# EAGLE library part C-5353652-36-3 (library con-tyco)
ETX Express COM Express Auto generated by make-symbol-device-package-bsdl.ulp Rev. 27 Source: http://catalog.tycoelectronics.com .. ENG_CS_889092_0.5mm_FH_Conn_0906.pdf http://nordic.kontron.com/searchresult/?searchterm=etxe_designguide_v1.4.pdf
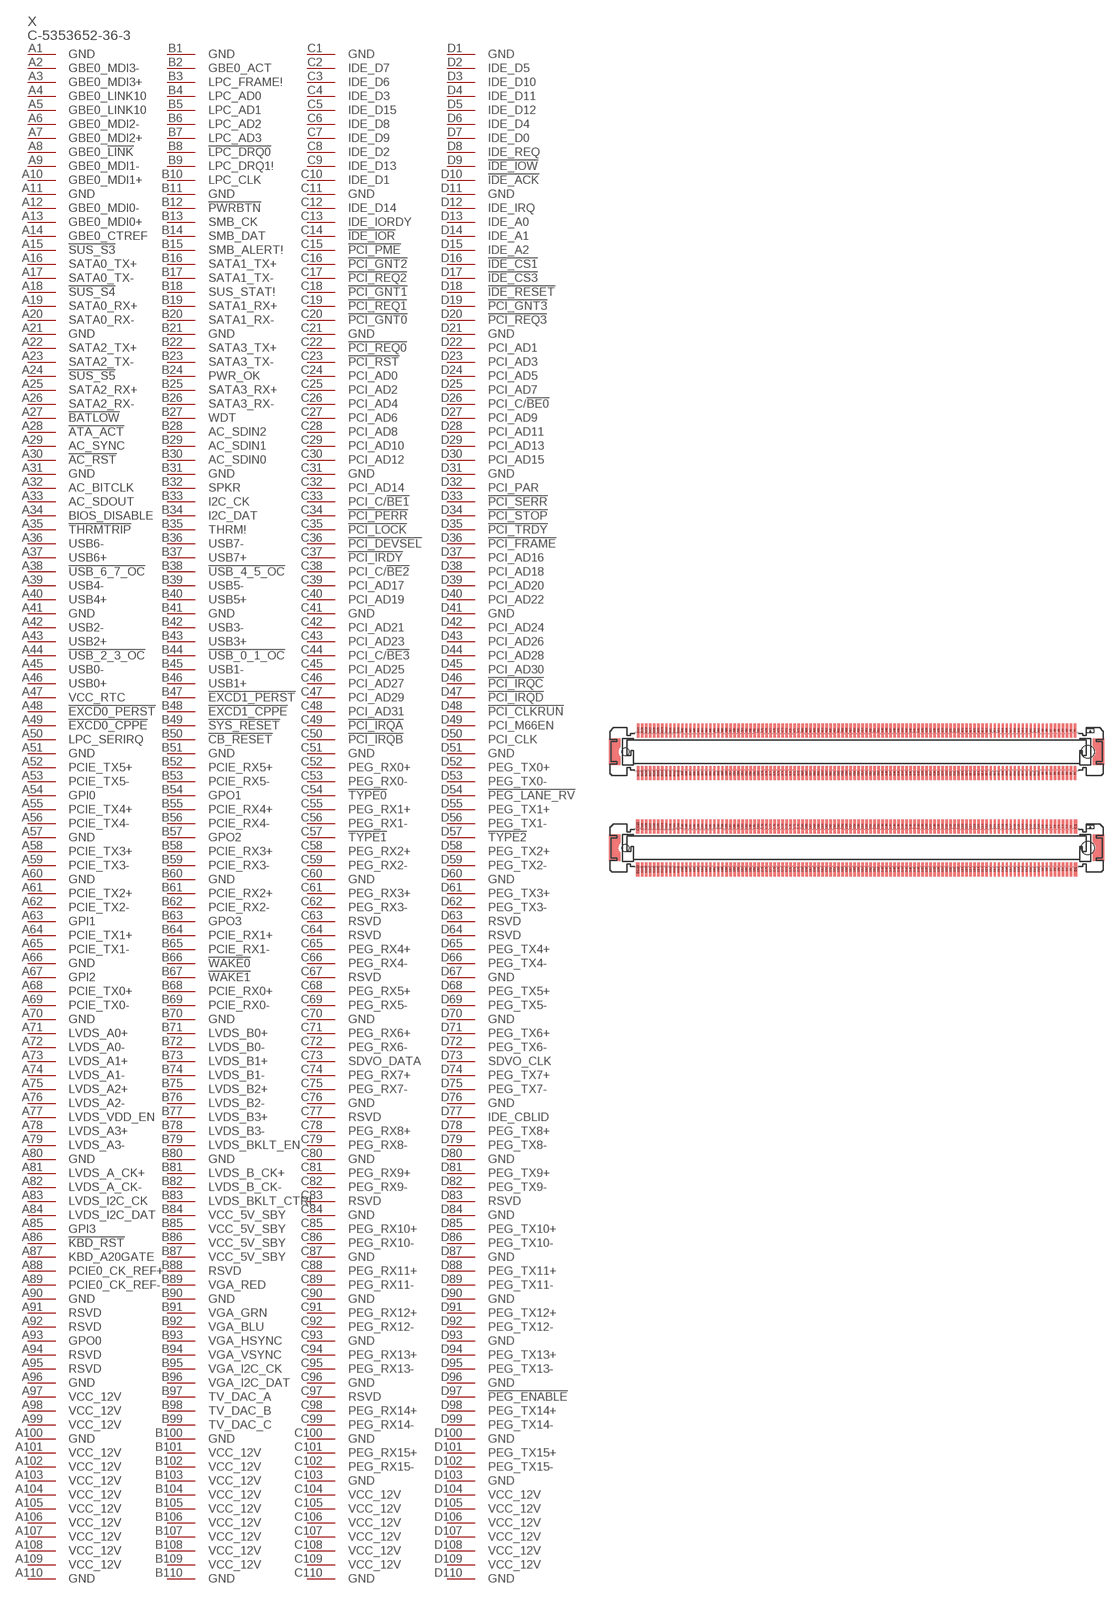
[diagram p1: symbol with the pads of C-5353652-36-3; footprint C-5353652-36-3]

Designator prefix X

## C-5353652-36-3 (OC_FARNELL: unknown; OC_NEWARK: unknown)  [C-5353652-36-3]
A1  GND  pas
A2  GBE0_MDI3-  pas
A3  GBE0_MDI3+  pas
A4  GBE0_LINK10  pas
A5  GBE0_LINK10  pas
A6  GBE0_MDI2-  pas
A7  GBE0_MDI2+  pas
A8  GBE0_!LINK  pas
A9  GBE0_MDI1-  pas
A10  GBE0_MDI1+  pas
A11  GND  pas
A12  GBE0_MDI0-  pas
A13  GBE0_MDI0+  pas
A14  GBE0_CTREF  pas
A15  !SUS_S3  pas
A16  SATA0_TX+  pas
A17  SATA0_TX-  pas
A18  !SUS_S4  pas
A19  SATA0_RX+  pas
A20  SATA0_RX-  pas
A21  GND  pas
A22  SATA2_TX+  pas
A23  SATA2_TX-  pas
A24  !SUS_S5  pas
A25  SATA2_RX+  pas
A26  SATA2_RX-  pas
A27  !BATLOW  pas
A28  !ATA_ACT  pas
A29  AC_SYNC  pas
A30  !AC_RST  pas
A31  GND  pas
A32  AC_BITCLK  pas
A33  AC_SDOUT  pas
A34  BIOS_DISABLE  pas
A35  !THRMTRIP  pas
A36  USB6-  pas
A37  USB6+  pas
A38  !USB_6_7_OC  pas
A39  USB4-  pas
A40  USB4+  pas
A41  GND  pas
A42  USB2-  pas
A43  USB2+  pas
A44  !USB_2_3_OC  pas
A45  USB0-  pas
A46  USB0+  pas
A47  VCC_RTC  pas
A48  !EXCD0_PERST  pas
A49  !EXCD0_CPPE  pas
A50  LPC_SERIRQ  pas
A51  GND  pas
A52  PCIE_TX5+  pas
A53  PCIE_TX5-  pas
A54  GPI0  pas
A55  PCIE_TX4+  pas
A56  PCIE_TX4-  pas
A57  GND  pas
A58  PCIE_TX3+  pas
A59  PCIE_TX3-  pas
A60  GND  pas
A61  PCIE_TX2+  pas
A62  PCIE_TX2-  pas
A63  GPI1  pas
A64  PCIE_TX1+  pas
A65  PCIE_TX1-  pas
A66  GND  pas
A67  GPI2  pas
A68  PCIE_TX0+  pas
A69  PCIE_TX0-  pas
A70  GND  pas
A71  LVDS_A0+  pas
A72  LVDS_A0-  pas
A73  LVDS_A1+  pas
A74  LVDS_A1-  pas
A75  LVDS_A2+  pas
A76  LVDS_A2-  pas
A77  LVDS_VDD_EN  pas
A78  LVDS_A3+  pas
A79  LVDS_A3-  pas
A80  GND  pas
A81  LVDS_A_CK+  pas
A82  LVDS_A_CK-  pas
A83  LVDS_I2C_CK  pas
A84  LVDS_I2C_DAT  pas
A85  GPI3  pas
A86  !KBD_RST  pas
A87  KBD_A20GATE  pas
A88  PCIE0_CK_REF+  pas
A89  PCIE0_CK_REF-  pas
A90  GND  pas
A91  RSVD  pas
A92  RSVD  pas
A93  GPO0  pas
A94  RSVD  pas
A95  RSVD  pas
A96  GND  pas
A97  VCC_12V  pas
A98  VCC_12V  pas
A99  VCC_12V  pas
A100  GND  pas
A101  VCC_12V  pas
A102  VCC_12V  pas
A103  VCC_12V  pas
A104  VCC_12V  pas
A105  VCC_12V  pas
A106  VCC_12V  pas
A107  VCC_12V  pas
A108  VCC_12V  pas
A109  VCC_12V  pas
A110  GND  pas
B1  GND  pas
B2  GBE0_ACT  pas
B3  LPC_FRAME!  pas
B4  LPC_AD0  pas
B5  LPC_AD1  pas
B6  LPC_AD2  pas
B7  LPC_AD3  pas
B8  !LPC_DRQ0  pas
B9  LPC_DRQ1!  pas
B10  LPC_CLK  pas
B11  GND  pas
B12  !PWRBTN  pas
B13  SMB_CK  pas
B14  SMB_DAT  pas
B15  SMB_ALERT!  pas
B16  SATA1_TX+  pas
B17  SATA1_TX-  pas
B18  SUS_STAT!  pas
B19  SATA1_RX+  pas
B20  SATA1_RX-  pas
B21  GND  pas
B22  SATA3_TX+  pas
B23  SATA3_TX-  pas
B24  PWR_OK  pas
B25  SATA3_RX+  pas
B26  SATA3_RX-  pas
B27  WDT  pas
B28  AC_SDIN2  pas
B29  AC_SDIN1  pas
B30  AC_SDIN0  pas
B31  GND  pas
B32  SPKR  pas
B33  I2C_CK  pas
B34  I2C_DAT  pas
B35  THRM!  pas
B36  USB7-  pas
B37  USB7+  pas
B38  !USB_4_5_OC  pas
B39  USB5-  pas
B40  USB5+  pas
B41  GND  pas
B42  USB3-  pas
B43  USB3+  pas
B44  !USB_0_1_OC  pas
B45  USB1-  pas
B46  USB1+  pas
B47  !EXCD1_PERST  pas
B48  !EXCD1_CPPE  pas
B49  !SYS_RESET  pas
B50  !CB_RESET  pas
B51  GND  pas
B52  PCIE_RX5+  pas
B53  PCIE_RX5-  pas
B54  GPO1  pas
B55  PCIE_RX4+  pas
B56  PCIE_RX4-  pas
B57  GPO2  pas
B58  PCIE_RX3+  pas
B59  PCIE_RX3-  pas
B60  GND  pas
B61  PCIE_RX2+  pas
B62  PCIE_RX2-  pas
B63  GPO3  pas
B64  PCIE_RX1+  pas
B65  PCIE_RX1-  pas
B66  !WAKE0  pas
B67  !WAKE1  pas
B68  PCIE_RX0+  pas
B69  PCIE_RX0-  pas
B70  GND  pas
B71  LVDS_B0+  pas
B72  LVDS_B0-  pas
B73  LVDS_B1+  pas
B74  LVDS_B1-  pas
B75  LVDS_B2+  pas
B76  LVDS_B2-  pas
B77  LVDS_B3+  pas
B78  LVDS_B3-  pas
B79  LVDS_BKLT_EN  pas
B80  GND  pas
B81  LVDS_B_CK+  pas
B82  LVDS_B_CK-  pas
B83  LVDS_BKLT_CTRL  pas
B84  VCC_5V_SBY  pas
B85  VCC_5V_SBY  pas
B86  VCC_5V_SBY  pas
B87  VCC_5V_SBY  pas
B88  RSVD  pas
B89  VGA_RED  pas
B90  GND  pas
B91  VGA_GRN  pas
B92  VGA_BLU  pas
B93  VGA_HSYNC  pas
B94  VGA_VSYNC  pas
B95  VGA_I2C_CK  pas
B96  VGA_I2C_DAT  pas
B97  TV_DAC_A  pas
B98  TV_DAC_B  pas
B99  TV_DAC_C  pas
B100  GND  pas
B101  VCC_12V  pas
B102  VCC_12V  pas
B103  VCC_12V  pas
B104  VCC_12V  pas
B105  VCC_12V  pas
B106  VCC_12V  pas
B107  VCC_12V  pas
B108  VCC_12V  pas
B109  VCC_12V  pas
B110  GND  pas
C1  GND  pas
C2  IDE_D7  pas
C3  IDE_D6  pas
C4  IDE_D3  pas
C5  IDE_D15  pas
C6  IDE_D8  pas
C7  IDE_D9  pas
C8  IDE_D2  pas
C9  IDE_D13  pas
C10  IDE_D1  pas
C11  GND  pas
C12  IDE_D14  pas
C13  IDE_IORDY  pas
C14  !IDE_IOR  pas
C15  !PCI_PME  pas
C16  !PCI_GNT2  pas
C17  !PCI_REQ2  pas
C18  !PCI_GNT1  pas
C19  !PCI_REQ1  pas
C20  !PCI_GNT0  pas
C21  GND  pas
C22  !PCI_REQ0  pas
C23  !PCI_RST  pas
C24  PCI_AD0  pas
C25  PCI_AD2  pas
C26  PCI_AD4  pas
C27  PCI_AD6  pas
C28  PCI_AD8  pas
C29  PCI_AD10  pas
C30  PCI_AD12  pas
C31  GND  pas
C32  PCI_AD14  pas
C33  PCI_C/!BE1  pas
C34  !PCI_PERR  pas
C35  !PCI_LOCK  pas
C36  !PCI_DEVSEL  pas
C37  !PCI_IRDY  pas
C38  PCI_C/!BE2  pas
C39  PCI_AD17  pas
C40  PCI_AD19  pas
C41  GND  pas
C42  PCI_AD21  pas
C43  PCI_AD23  pas
C44  PCI_C/!BE3  pas
C45  PCI_AD25  pas
C46  PCI_AD27  pas
C47  PCI_AD29  pas
C48  PCI_AD31  pas
C49  !PCI_IRQA  pas
C50  !PCI_IRQB  pas
C51  GND  pas
C52  PEG_RX0+  pas
C53  PEG_RX0-  pas
C54  !TYPE0  pas
C55  PEG_RX1+  pas
C56  PEG_RX1-  pas
C57  !TYPE1  pas
C58  PEG_RX2+  pas
C59  PEG_RX2-  pas
C60  GND  pas
C61  PEG_RX3+  pas
C62  PEG_RX3-  pas
C63  RSVD  pas
C64  RSVD  pas
C65  PEG_RX4+  pas
C66  PEG_RX4-  pas
C67  RSVD  pas
C68  PEG_RX5+  pas
C69  PEG_RX5-  pas
C70  GND  pas
C71  PEG_RX6+  pas
C72  PEG_RX6-  pas
C73  SDVO_DATA  pas
C74  PEG_RX7+  pas
C75  PEG_RX7-  pas
C76  GND  pas
C77  RSVD  pas
C78  PEG_RX8+  pas
C79  PEG_RX8-  pas
C80  GND  pas
C81  PEG_RX9+  pas
C82  PEG_RX9-  pas
C83  RSVD  pas
C84  GND  pas
C85  PEG_RX10+  pas
C86  PEG_RX10-  pas
C87  GND  pas
C88  PEG_RX11+  pas
C89  PEG_RX11-  pas
C90  GND  pas
C91  PEG_RX12+  pas
C92  PEG_RX12-  pas
C93  GND  pas
C94  PEG_RX13+  pas
C95  PEG_RX13-  pas
C96  GND  pas
C97  RSVD  pas
C98  PEG_RX14+  pas
C99  PEG_RX14-  pas
C100  GND  pas
C101  PEG_RX15+  pas
C102  PEG_RX15-  pas
C103  GND  pas
C104  VCC_12V  pas
C105  VCC_12V  pas
C106  VCC_12V  pas
C107  VCC_12V  pas
C108  VCC_12V  pas
C109  VCC_12V  pas
C110  GND  pas
D1  GND  pas
D2  IDE_D5  pas
D3  IDE_D10  pas
D4  IDE_D11  pas
D5  IDE_D12  pas
D6  IDE_D4  pas
D7  IDE_D0  pas
D8  IDE_REQ  pas
D9  !IDE_IOW  pas
D10  !IDE_ACK  pas
D11  GND  pas
D12  IDE_IRQ  pas
D13  IDE_A0  pas
D14  IDE_A1  pas
D15  IDE_A2  pas
D16  !IDE_CS1  pas
D17  !IDE_CS3  pas
D18  !IDE_RESET  pas
D19  !PCI_GNT3  pas
D20  !PCI_REQ3  pas
D21  GND  pas
D22  PCI_AD1  pas
D23  PCI_AD3  pas
D24  PCI_AD5  pas
D25  PCI_AD7  pas
D26  PCI_C/!BE0  pas
D27  PCI_AD9  pas
D28  PCI_AD11  pas
D29  PCI_AD13  pas
D30  PCI_AD15  pas
D31  GND  pas
D32  PCI_PAR  pas
D33  !PCI_SERR  pas
D34  !PCI_STOP  pas
D35  !PCI_TRDY  pas
D36  !PCI_FRAME  pas
D37  PCI_AD16  pas
D38  PCI_AD18  pas
D39  PCI_AD20  pas
D40  PCI_AD22  pas
D41  GND  pas
D42  PCI_AD24  pas
D43  PCI_AD26  pas
D44  PCI_AD28  pas
D45  PCI_AD30  pas
D46  !PCI_IRQC  pas
D47  !PCI_IRQD  pas
D48  !PCI_CLKRUN  pas
D49  PCI_M66EN  pas
D50  PCI_CLK  pas
D51  GND  pas
D52  PEG_TX0+  pas
D53  PEG_TX0-  pas
D54  !PEG_LANE_RV  pas
D55  PEG_TX1+  pas
D56  PEG_TX1-  pas
D57  !TYPE2  pas
D58  PEG_TX2+  pas
D59  PEG_TX2-  pas
D60  GND  pas
D61  PEG_TX3+  pas
D62  PEG_TX3-  pas
D63  RSVD  pas
D64  RSVD  pas
D65  PEG_TX4+  pas
D66  PEG_TX4-  pas
D67  GND  pas
D68  PEG_TX5+  pas
D69  PEG_TX5-  pas
D70  GND  pas
D71  PEG_TX6+  pas
D72  PEG_TX6-  pas
D73  SDVO_CLK  pas
D74  PEG_TX7+  pas
D75  PEG_TX7-  pas
D76  GND  pas
D77  IDE_CBLID  pas
D78  PEG_TX8+  pas
D79  PEG_TX8-  pas
D80  GND  pas
D81  PEG_TX9+  pas
D82  PEG_TX9-  pas
D83  RSVD  pas
D84  GND  pas
D85  PEG_TX10+  pas
D86  PEG_TX10-  pas
D87  GND  pas
D88  PEG_TX11+  pas
D89  PEG_TX11-  pas
D90  GND  pas
D91  PEG_TX12+  pas
D92  PEG_TX12-  pas
D93  GND  pas
D94  PEG_TX13+  pas
D95  PEG_TX13-  pas
D96  GND  pas
D97  !PEG_ENABLE  pas
D98  PEG_TX14+  pas
D99  PEG_TX14-  pas
D100  GND  pas
D101  PEG_TX15+  pas
D102  PEG_TX15-  pas
D103  GND  pas
D104  VCC_12V  pas
D105  VCC_12V  pas
D106  VCC_12V  pas
D107  VCC_12V  pas
D108  VCC_12V  pas
D109  VCC_12V  pas
D110  GND  pas

## Footprint C-5353652-36-3 (pad centres in mm)
ComExpress (ETXexpress) Source: http://catalog.tycoelectronics.com .. ENG_CS_889092_0.5mm_FH_Conn_0906.pdf
smd 0.3 x 1.75: A1 27.25,8.675; A2 26.75,8.675; A3 26.25,8.675; A4 25.75,8.675; A5 25.25,8.675; A6 24.75,8.675; A7 24.25,8.675; A8 23.75,8.675; A9 23.25,8.675; A10 22.75,8.675; A11 22.25,8.675; A12 21.75,8.675; A13 21.25,8.675; A14 20.75,8.675; A15 20.25,8.675; A16 19.75,8.675; A17 19.25,8.675; A18 18.75,8.675; A19 18.25,8.675; A20 17.75,8.675; A21 17.25,8.675; A22 16.75,8.675; A23 16.25,8.675; A24 15.75,8.675; A25 15.25,8.675; A26 14.75,8.675; A27 14.25,8.675; A28 13.75,8.675; A29 13.25,8.675; A30 12.75,8.675; A31 12.25,8.675; A32 11.75,8.675; A33 11.25,8.675; A34 10.75,8.675; A35 10.25,8.675; A36 9.75,8.675; A37 9.25,8.675; A38 8.75,8.675; A39 8.25,8.675; A40 7.75,8.675; A41 7.25,8.675; A42 6.75,8.675; A43 6.25,8.675; A44 5.75,8.675; A45 5.25,8.675; A46 4.75,8.675; A47 4.25,8.675; A48 3.75,8.675; A49 3.25,8.675; A50 2.75,8.675; A51 2.25,8.675; A52 1.75,8.675; A53 1.25,8.675; A54 0.75,8.675; A55 0.25,8.675; A56 -0.25,8.675; A57 -0.75,8.675; A58 -1.25,8.675; A59 -1.75,8.675; A60 -2.25,8.675; A61 -2.75,8.675; A62 -3.25,8.675; A63 -3.75,8.675; A64 -4.25,8.675; A65 -4.75,8.675; A66 -5.25,8.675; A67 -5.75,8.675; A68 -6.25,8.675; A69 -6.75,8.675; A70 -7.25,8.675; A71 -7.75,8.675; A72 -8.25,8.675; A73 -8.75,8.675; A74 -9.25,8.675; A75 -9.75,8.675; A76 -10.25,8.675; A77 -10.75,8.675; A78 -11.25,8.675; A79 -11.75,8.675; A80 -12.25,8.675; A81 -12.75,8.675; A82 -13.25,8.675; A83 -13.75,8.675; A84 -14.25,8.675; A85 -14.75,8.675; A86 -15.25,8.675; A87 -15.75,8.675; A88 -16.25,8.675; A89 -16.75,8.675; A90 -17.25,8.675; A91 -17.75,8.675; A92 -18.25,8.675; A93 -18.75,8.675; A94 -19.25,8.675; A95 -19.75,8.675; A96 -20.25,8.675; A97 -20.75,8.675; A98 -21.25,8.675; A99 -21.75,8.675; A100 -22.25,8.675; A101 -22.75,8.675; A102 -23.25,8.675; A103 -23.75,8.675; A104 -24.25,8.675; A105 -24.75,8.675; A106 -25.25,8.675; A107 -25.75,8.675; A108 -26.25,8.675; A109 -26.75,8.675; A110 -27.25,8.675; B1 27.25,3.325; B2 26.75,3.325; B3 26.25,3.325; B4 25.75,3.325; B5 25.25,3.325; B6 24.75,3.325; B7 24.25,3.325; B8 23.75,3.325; B9 23.25,3.325; B10 22.75,3.325; B11 22.25,3.325; B12 21.75,3.325; B13 21.25,3.325; B14 20.75,3.325; B15 20.25,3.325; B16 19.75,3.325; B17 19.25,3.325; B18 18.75,3.325; B19 18.25,3.325; B20 17.75,3.325; B21 17.25,3.325; B22 16.75,3.325; B23 16.25,3.325; B24 15.75,3.325; B25 15.25,3.325; B26 14.75,3.325; B27 14.25,3.325; B28 13.75,3.325; B29 13.25,3.325; B30 12.75,3.325; B31 12.25,3.325; B32 11.75,3.325; B33 11.25,3.325; B34 10.75,3.325; B35 10.25,3.325; B36 9.75,3.325; B37 9.25,3.325; B38 8.75,3.325; B39 8.25,3.325; B40 7.75,3.325; B41 7.25,3.325; B42 6.75,3.325; B43 6.25,3.325; B44 5.75,3.325; B45 5.25,3.325; B46 4.75,3.325; B47 4.25,3.325; B48 3.75,3.325; B49 3.25,3.325; B50 2.75,3.325; B51 2.25,3.325; B52 1.75,3.325; B53 1.25,3.325; B54 0.75,3.325; B55 0.25,3.325; B56 -0.25,3.325; B57 -0.75,3.325; B58 -1.25,3.325; B59 -1.75,3.325; B60 -2.25,3.325; B61 -2.75,3.325; B62 -3.25,3.325; B63 -3.75,3.325; B64 -4.25,3.325; B65 -4.75,3.325; B66 -5.25,3.325; B67 -5.75,3.325; B68 -6.25,3.325; B69 -6.75,3.325; B70 -7.25,3.325; B71 -7.75,3.325; B72 -8.25,3.325; B73 -8.75,3.325; B74 -9.25,3.325; B75 -9.75,3.325; B76 -10.25,3.325; B77 -10.75,3.325; B78 -11.25,3.325; B79 -11.75,3.325; B80 -12.25,3.325; B81 -12.75,3.325; B82 -13.25,3.325; B83 -13.75,3.325; B84 -14.25,3.325; B85 -14.75,3.325; B86 -15.25,3.325; B87 -15.75,3.325; B88 -16.25,3.325; B89 -16.75,3.325; B90 -17.25,3.325; B91 -17.75,3.325; B92 -18.25,3.325; B93 -18.75,3.325; B94 -19.25,3.325; B95 -19.75,3.325; B96 -20.25,3.325; B97 -20.75,3.325; B98 -21.25,3.325; B99 -21.75,3.325; B100 -22.25,3.325; B101 -22.75,3.325; B102 -23.25,3.325; B103 -23.75,3.325; B104 -24.25,3.325; B105 -24.75,3.325; B106 -25.25,3.325; B107 -25.75,3.325; B108 -26.25,3.325; B109 -26.75,3.325; B110 -27.25,3.325; C2 26.75,-3.325; C3 26.25,-3.325; C4 25.75,-3.325; C5 25.25,-3.325; C6 24.75,-3.325; C7 24.25,-3.325; C8 23.75,-3.325; C9 23.25,-3.325; C10 22.75,-3.325; C11 22.25,-3.325; C12 21.75,-3.325; C13 21.25,-3.325; C14 20.75,-3.325; C15 20.25,-3.325; C16 19.75,-3.325; C17 19.25,-3.325; C18 18.75,-3.325; C19 18.25,-3.325; C20 17.75,-3.325; C21 17.25,-3.325; C22 16.75,-3.325; C23 16.25,-3.325; C24 15.75,-3.325; C25 15.25,-3.325; C26 14.75,-3.325; C27 14.25,-3.325; C28 13.75,-3.325; C29 13.25,-3.325; C30 12.75,-3.325; C31 12.25,-3.325; C32 11.75,-3.325; C33 11.25,-3.325; C34 10.75,-3.325; C35 10.25,-3.325; C36 9.75,-3.325; C37 9.25,-3.325; C38 8.75,-3.325; C39 8.25,-3.325; C40 7.75,-3.325; C41 7.25,-3.325; C42 6.75,-3.325; C43 6.25,-3.325; C44 5.75,-3.325; C45 5.25,-3.325; C46 4.75,-3.325; C47 4.25,-3.325; C48 3.75,-3.325; C49 3.25,-3.325; C50 2.75,-3.325; C51 2.25,-3.325; C52 1.75,-3.325; C53 1.25,-3.325; C54 0.75,-3.325; C55 0.25,-3.325; C56 -0.25,-3.325; C57 -0.75,-3.325; C58 -1.25,-3.325; C59 -1.75,-3.325; C60 -2.25,-3.325; C61 -2.75,-3.325; C62 -3.25,-3.325; C63 -3.75,-3.325; C64 -4.25,-3.325; C65 -4.75,-3.325; C66 -5.25,-3.325; C67 -5.75,-3.325; C68 -6.25,-3.325; C69 -6.75,-3.325; C70 -7.25,-3.325; C71 -7.75,-3.325; C72 -8.25,-3.325; C73 -8.75,-3.325; C74 -9.25,-3.325; C75 -9.75,-3.325; C76 -10.25,-3.325; C77 -10.75,-3.325; C78 -11.25,-3.325; C79 -11.75,-3.325; C80 -12.25,-3.325; C81 -12.75,-3.325; C82 -13.25,-3.325; C83 -13.75,-3.325; C84 -14.25,-3.325; C85 -14.75,-3.325; C86 -15.25,-3.325; C87 -15.75,-3.325; C88 -16.25,-3.325; C89 -16.75,-3.325; C90 -17.25,-3.325; C91 -17.75,-3.325; C92 -18.25,-3.325; C93 -18.75,-3.325; C94 -19.25,-3.325; C95 -19.75,-3.325; C96 -20.25,-3.325; C97 -20.75,-3.325; C98 -21.25,-3.325; C99 -21.75,-3.325; C100 -22.25,-3.325; C101 -22.75,-3.325; C102 -23.25,-3.325; C103 -23.75,-3.325; C104 -24.25,-3.325; C105 -24.75,-3.325; C106 -25.25,-3.325; C107 -25.75,-3.325; C108 -26.25,-3.325; C109 -26.75,-3.325; D2 26.75,-8.675; D3 26.25,-8.675; D4 25.75,-8.675; D5 25.25,-8.675; D6 24.75,-8.675; D7 24.25,-8.675; D8 23.75,-8.675; D9 23.25,-8.675; D10 22.75,-8.675; D11 22.25,-8.675; D12 21.75,-8.675; D13 21.25,-8.675; D14 20.75,-8.675; D15 20.25,-8.675; D16 19.75,-8.675; D17 19.25,-8.675; D18 18.75,-8.675; D19 18.25,-8.675; D20 17.75,-8.675; D21 17.25,-8.675; D22 16.75,-8.675; D23 16.25,-8.675; D24 15.75,-8.675; D25 15.25,-8.675; D26 14.75,-8.675; D27 14.25,-8.675; D28 13.75,-8.675; D29 13.25,-8.675; D30 12.75,-8.675; D31 12.25,-8.675; D32 11.75,-8.675; D33 11.25,-8.675; D34 10.75,-8.675; D35 10.25,-8.675; D36 9.75,-8.675; D37 9.25,-8.675; D38 8.75,-8.675; D39 8.25,-8.675; D40 7.75,-8.675; D41 7.25,-8.675; D42 6.75,-8.675; D43 6.25,-8.675; D44 5.75,-8.675; D45 5.25,-8.675; D46 4.75,-8.675; D47 4.25,-8.675; D48 3.75,-8.675; D49 3.25,-8.675; D50 2.75,-8.675; D51 2.25,-8.675; D52 1.75,-8.675; D53 1.25,-8.675; D54 0.75,-8.675; D55 0.25,-8.675; D56 -0.25,-8.675; D57 -0.75,-8.675; D58 -1.25,-8.675; D59 -1.75,-8.675; D60 -2.25,-8.675; D61 -2.75,-8.675; D62 -3.25,-8.675; D63 -3.75,-8.675; D64 -4.25,-8.675; D65 -4.75,-8.675; D66 -5.25,-8.675; D67 -5.75,-8.675; D68 -6.25,-8.675; D69 -6.75,-8.675; D70 -7.25,-8.675; D71 -7.75,-8.675; D72 -8.25,-8.675; D73 -8.75,-8.675; D74 -9.25,-8.675; D75 -9.75,-8.675; D76 -10.25,-8.675; D77 -10.75,-8.675; D78 -11.25,-8.675; D79 -11.75,-8.675; D80 -12.25,-8.675; D81 -12.75,-8.675; D82 -13.25,-8.675; D83 -13.75,-8.675; D84 -14.25,-8.675; D85 -14.75,-8.675; D86 -15.25,-8.675; D87 -15.75,-8.675; D88 -16.25,-8.675; D89 -16.75,-8.675; D90 -17.25,-8.675; D91 -17.75,-8.675; D92 -18.25,-8.675; D93 -18.75,-8.675; D94 -19.25,-8.675; D95 -19.75,-8.675; D96 -20.25,-8.675; D97 -20.75,-8.675; D98 -21.25,-8.675; D99 -21.75,-8.675; D100 -22.25,-8.675; D101 -22.75,-8.675; D102 -23.25,-8.675; D103 -23.75,-8.675; D104 -24.25,-8.675; D105 -24.75,-8.675; D106 -25.25,-8.675; D107 -25.75,-8.675; D108 -26.25,-8.675; D109 -26.75,-8.675
smd 0.45 x 1.75: C1 27.325,-3.325; C110 -27.325,-3.325; D1 27.325,-8.675; D110 -27.325,-8.675
hole 0.9 at -28.85,-6
hole 1.6 at 28.85,-6
hole 0.9 at -28.85,6
hole 1.6 at 28.85,6
hole 0.9 at -28.85,-6
hole 1.6 at 28.85,-6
